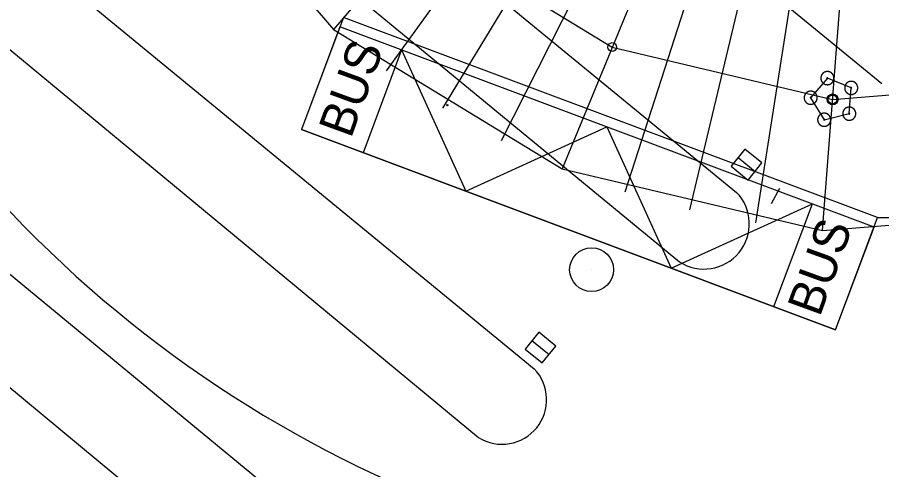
# Model space of a CAD drawing. Extents: x -438303 to -437792, y -1133191 to -1132731.
# Drawn here: x -438077.75 to -438058.05, y -1132976.36 to -1132966.05 of the extents above; entities that cross this region are included whole.
import ezdxf

# ---------------------------------------------------------------- set-up
doc = ezdxf.new("R2010")
doc.units = 0
for name, color, linetype in [('MOBILIÁŘ', 7, 'Continuous'), ('OSY', 7, 'Continuous'), ('SILNA 1', 7, 'Continuous'), ('SILNA 2', 7, 'Continuous'), ('TENKA', 7, 'Continuous'), ('Vrstva 1', 7, 'Continuous'), ('Vrstva 10', 7, 'Continuous'), ('Vrstva 27', 7, 'Continuous')]:
    doc.layers.add(name, color=color, linetype=linetype)

# ---------------------------------------------------------------- blocks, each defined once
blk = doc.blocks.new('A$C32EE4163')
at = {"layer": 'SILNA 1'}
for radius in [1.25, 1.25, 1.13, 1.13]:
    blk.add_circle((0, 0), radius, dxfattribs=at)
blk = doc.blocks.new('A$C7A6F5A01')
at = {"layer": 'Vrstva 1'}
for p, q in [((-20, 32), (-39, 0)), ((-39, 0), (-20, -35)), ((18, 32), (-20, 32)), ((40, 0), (18, 32)), ((18, -35), (40, 0)), ((-20, -35), (18, -35))]:
    blk.add_line(p, q, dxfattribs=at)
for points in [[(1497, 0), (1491, 133), (1481, 203), (1479, 219), (1476, 236), (1474, 253), (1471, 269), (1468, 286), (1465, 302), (1461, 319), (1458, 335), (1454, 351), (1450, 367), (1446, 383), (1442, 399), (1437, 415), (1432, 431), (1428, 447), (1423, 463), (1418, 478), (1412, 494), (1407, 509), (1401, 524), (1396, 540), (1390, 555), (1383, 570), (1377, 585), (1371, 600), (1364, 615), (1358, 630), (1351, 644), (1344, 659), (1336, 673), (1329, 688), (1322, 702), (1314, 716), (1306, 730), (1298, 744), (1290, 758), (1282, 772), (1274, 786), (1265, 799), (1256, 813), (1248, 826), (1239, 840), (1229, 853), (1220, 866), (1211, 879), (1201, 892), (1192, 905), (1182, 917), (1172, 930), (1162, 942), (1152, 955), (1142, 967), (1131, 979), (1121, 991), (1110, 1003), (1099, 1015), (1088, 1026), (1077, 1038), (1066, 1049), (1055, 1061), (1044, 1072), (1032, 1083), (1020, 1094), (1009, 1105), (997, 1115), (985, 1126), (973, 1136), (961, 1147), (948, 1157), (936, 1167), (923, 1177), (911, 1186), (898, 1196), (885, 1206), (872, 1215), (859, 1224), (846, 1233), (833, 1242), (819, 1251), (806, 1260), (792, 1268), (779, 1277), (765, 1285), (751, 1293), (737, 1301), (723, 1309), (709, 1317), (695, 1324), (681, 1332), (666, 1339), (652, 1346), (637, 1353), (623, 1360), (608, 1366), (593, 1373), (578, 1379), (563, 1385), (548, 1391), (533, 1397), (518, 1403), (503, 1409), (487, 1414), (472, 1419), (456, 1424), (441, 1429), (425, 1434), (409, 1438), (394, 1443), (378, 1447), (362, 1451), (346, 1455), (330, 1459), (314, 1462), (298, 1466), (281, 1469), (265, 1472), (249, 1475), (232, 1478), (216, 1480), (200, 1482), (183, 1485), (166, 1487), (150, 1488), (133, 1490), (116, 1491), (99, 1493), (83, 1494), (66, 1495), (-67, 1495), (-85, 1494), (-102, 1493), (-120, 1491), (-137, 1490), (-154, 1488), (-172, 1486), (-189, 1484), (-206, 1482), (-223, 1479), (-240, 1477), (-257, 1474), (-274, 1471), (-290, 1467), (-307, 1464), (-324, 1460), (-341, 1457), (-357, 1453), (-374, 1448), (-390, 1444), (-406, 1440), (-422, 1435), (-439, 1430), (-455, 1425), (-471, 1420), (-487, 1414), (-503, 1409), (-518, 1403), (-534, 1397), (-550, 1391), (-565, 1385), (-581, 1378), (-596, 1372), (-611, 1365), (-626, 1358), (-642, 1351), (-657, 1344), (-671, 1336), (-686, 1329), (-701, 1321), (-716, 1313), (-730, 1305), (-744, 1297), (-759, 1289), (-773, 1280), (-787, 1272), (-801, 1263), (-815, 1254), (-829, 1245), (-843, 1236), (-856, 1226), (-870, 1217), (-883, 1207), (-896, 1197), (-909, 1187), (-922, 1177), (-935, 1167), (-948, 1156), (-961, 1146), (-973, 1135), (-986, 1124), (-998, 1114), (-1010, 1102), (-1023, 1091), (-1035, 1080), (-1046, 1069), (-1058, 1057), (-1070, 1045), (-1081, 1033), (-1092, 1021), (-1104, 1009), (-1115, 997), (-1126, 985), (-1136, 972), (-1147, 960), (-1158, 947), (-1168, 934), (-1178, 921), (-1188, 908), (-1198, 895), (-1208, 882), (-1218, 869), (-1227, 855), (-1237, 841), (-1246, 828), (-1255, 814), (-1264, 800), (-1273, 786), (-1281, 772), (-1290, 758), (-1298, 743), (-1306, 729), (-1314, 714), (-1322, 700), (-1330, 685), (-1338, 670), (-1345, 655), (-1352, 640), (-1359, 625), (-1366, 610), (-1373, 594), (-1379, 579), (-1386, 564), (-1392, 548), (-1398, 532), (-1404, 517), (-1410, 501), (-1415, 485), (-1420, 469), (-1426, 453), (-1431, 437), (-1435, 420), (-1440, 404), (-1445, 388), (-1449, 371), (-1453, 355), (-1457, 338), (-1461, 321), (-1464, 304), (-1467, 288), (-1471, 271), (-1474, 254), (-1476, 237), (-1479, 220), (-1481, 202), (-1484, 185), (-1486, 168), (-1487, 150), (-1489, 133), (-1495, 67), (-1495, -66), (-1489, -136), (-1488, -153), (-1486, -170), (-1484, -186), (-1482, -203), (-1479, -220), (-1477, -236), (-1474, -253), (-1472, -269), (-1469, -285), (-1465, -302), (-1462, -318), (-1458, -334), (-1455, -350), (-1451, -366), (-1447, -382), (-1442, -398), (-1438, -414), (-1433, -429), (-1429, -445), (-1424, -461), (-1419, -476), (-1413, -492), (-1408, -507), (-1402, -522), (-1397, -537), (-1391, -552), (-1385, -568), (-1378, -582), (-1372, -597), (-1366, -612), (-1359, -627), (-1352, -641), (-1345, -656), (-1338, -670), (-1330, -685), (-1323, -699), (-1315, -713), (-1308, -727), (-1300, -741), (-1292, -755), (-1283, -769), (-1275, -783), (-1267, -796), (-1258, -810), (-1249, -823), (-1240, -837), (-1231, -850), (-1222, -863), (-1213, -876), (-1203, -889), (-1193, -902), (-1184, -914), (-1174, -927), (-1164, -939), (-1154, -952), (-1143, -964), (-1133, -976), (-1122, -988), (-1112, -1000), (-1101, -1012), (-1090, -1024), (-1079, -1035), (-1068, -1047), (-1057, -1058), (-1045, -1069), (-1034, -1080), (-1022, -1091), (-1010, -1102), (-999, -1113), (-987, -1124), (-974, -1134), (-962, -1145), (-950, -1155), (-938, -1165), (-925, -1175), (-912, -1185), (-900, -1194), (-887, -1204), (-874, -1213), (-861, -1223), (-848, -1232), (-834, -1241), (-821, -1250), (-808, -1259), (-794, -1267), (-780, -1276), (-767, -1284), (-753, -1292), (-739, -1300), (-725, -1308), (-711, -1316), (-696, -1324), (-682, -1331), (-668, -1338), (-653, -1346), (-639, -1353), (-624, -1360), (-609, -1366), (-595, -1373), (-580, -1379), (-565, -1385), (-550, -1392), (-534, -1397), (-519, -1403), (-504, -1409), (-489, -1414), (-473, -1420), (-458, -1425), (-442, -1430), (-426, -1434), (-411, -1439), (-395, -1444), (-379, -1448), (-363, -1452), (-347, -1456), (-331, -1460), (-315, -1463), (-299, -1467), (-283, -1470), (-266, -1473), (-250, -1476), (-233, -1479), (-217, -1481), (-200, -1484), (-184, -1486), (-167, -1488), (-151, -1490), (-134, -1491), (-67, -1495), (-1, -1495), (17, -1495), (34, -1494), (51, -1494), (68, -1494), (85, -1493), (103, -1492), (120, -1491), (137, -1489), (154, -1488), (171, -1486), (188, -1484), (204, -1482), (221, -1480), (238, -1477), (255, -1474), (271, -1471), (288, -1468), (305, -1465), (321, -1461), (338, -1458), (354, -1454), (370, -1450), (387, -1446), (403, -1441), (419, -1436), (435, -1432), (451, -1427), (467, -1422), (483, -1416), (498, -1411), (514, -1405), (530, -1399), (545, -1393), (561, -1387), (576, -1381), (592, -1374), (607, -1367), (622, -1361), (637, -1354), (652, -1346), (667, -1339), (682, -1331), (697, -1324), (711, -1316), (726, -1308), (740, -1300), (755, -1291), (769, -1283), (783, -1274), (797, -1265), (811, -1257), (825, -1247), (839, -1238), (852, -1229), (866, -1219), (879, -1210), (893, -1200), (906, -1190), (919, -1180), (932, -1169), (945, -1159), (958, -1149), (970, -1138), (983, -1127), (995, -1116), (1008, -1105), (1020, -1094), (1032, -1082), (1044, -1071), (1056, -1059), (1067, -1048), (1079, -1036), (1090, -1024), (1102, -1012), (1113, -999), (1124, -987), (1135, -975), (1146, -962), (1156, -949), (1167, -936), (1177, -923), (1187, -910), (1197, -897), (1207, -884), (1217, -870), (1227, -857), (1236, -843), (1246, -830), (1255, -816), (1264, -802), (1273, -788), (1281, -773), (1290, -759), (1298, -745), (1307, -730), (1315, -716), (1323, -701), (1330, -686), (1338, -671), (1346, -656), (1353, -641), (1360, -626), (1367, -611), (1374, -595), (1380, -580), (1387, -564), (1393, -549), (1399, -533), (1405, -517), (1410, -501), (1416, -486), (1421, -469), (1427, -453), (1431, -437), (1436, -421), (1441, -405), (1445, -388), (1450, -372), (1454, -355), (1457, -338), (1461, -322), (1465, -305), (1468, -288), (1471, -271), (1474, -254), (1476, -237), (1479, -220), (1481, -203), (1491, -136), (1494, -66)], [(-1, -101), (18, -98), (37, -92), (39, -91), (41, -90), (43, -89), (45, -88), (47, -87), (49, -86), (51, -85), (53, -84), (55, -83), (57, -82), (58, -81), (60, -80), (62, -78), (63, -77), (65, -76), (67, -75), (68, -73), (70, -72), (71, -70), (73, -69), (74, -68), (75, -66), (77, -65), (78, -63), (79, -62), (80, -60), (82, -59), (83, -57), (84, -55), (85, -54), (86, -52), (87, -50), (88, -49), (89, -47), (90, -45), (90, -44), (91, -42), (92, -40), (93, -38), (94, -37), (94, -35), (95, -33), (95, -31), (96, -29), (97, -28), (97, -26), (98, -24), (98, -22), (98, -20), (99, -18), (99, -16), (99, -15), (100, -13), (100, -11), (100, -9), (100, -7), (100, -5), (100, -3), (100, -1), (100, 1), (100, 2), (100, 4), (100, 6), (100, 8), (100, 10), (100, 12), (99, 14), (99, 16), (99, 18), (98, 19), (98, 21), (98, 23), (97, 25), (97, 27), (96, 29), (95, 31), (95, 32), (94, 34), (94, 36), (93, 38), (92, 40), (91, 41), (91, 43), (90, 45), (89, 47), (88, 48), (87, 50), (86, 52), (85, 53), (84, 55), (83, 57), (82, 58), (81, 60), (79, 61), (78, 63), (77, 64), (76, 66), (74, 67), (73, 69), (71, 70), (70, 72), (69, 73), (67, 74), (66, 76), (64, 77), (62, 78), (61, 79), (59, 81), (57, 82), (56, 83), (54, 84), (52, 85), (50, 86), (48, 87), (46, 88), (44, 89), (42, 90), (40, 91), (38, 92), (36, 93), (34, 94), (32, 94), (30, 95), (27, 96), (25, 96), (23, 97), (21, 98), (18, 98), (-17, 98), (-19, 98), (-21, 97), (-23, 96), (-26, 96), (-28, 95), (-30, 94), (-32, 94), (-34, 93), (-36, 92), (-38, 91), (-40, 90), (-42, 89), (-44, 88), (-46, 87), (-48, 86), (-50, 85), (-52, 84), (-54, 83), (-55, 82), (-57, 81), (-59, 80), (-60, 78), (-62, 77), (-64, 76), (-65, 75), (-67, 73), (-68, 72), (-70, 71), (-71, 69), (-72, 68), (-74, 66), (-75, 65), (-76, 63), (-78, 62), (-79, 60), (-80, 59), (-81, 57), (-82, 56), (-83, 54), (-85, 52), (-86, 51), (-87, 49), (-87, 47), (-88, 46), (-89, 44), (-90, 42), (-91, 41), (-92, 39), (-92, 37), (-93, 35), (-94, 34), (-94, 32), (-95, 30), (-96, 28), (-96, 26), (-97, 25), (-97, 23), (-98, 21), (-98, 19), (-98, 17), (-99, 15), (-99, 13), (-99, 12), (-99, 10), (-100, 8), (-100, 6), (-100, 4), (-100, 2), (-100, 0), (-100, -2), (-100, -3), (-100, -5), (-100, -7), (-100, -9), (-99, -11), (-99, -13), (-99, -15), (-99, -17), (-98, -18), (-98, -20), (-98, -22), (-97, -24), (-97, -26), (-96, -28), (-96, -29), (-95, -31), (-94, -33), (-94, -35), (-93, -37), (-92, -38), (-92, -40), (-91, -42), (-90, -44), (-89, -45), (-88, -47), (-87, -49), (-86, -50), (-85, -52), (-84, -54), (-83, -55), (-82, -57), (-80, -58), (-79, -60), (-78, -62), (-77, -63), (-75, -65), (-74, -66), (-72, -68), (-71, -69), (-70, -71), (-68, -72), (-66, -73), (-65, -75), (-63, -76), (-61, -77), (-60, -79), (-58, -80), (-56, -81), (-54, -82), (-52, -83), (-50, -85), (-48, -86), (-46, -87), (-44, -88), (-42, -89), (-40, -90), (-38, -91), (-36, -92), (-17, -98)]]:
    blk.add_lwpolyline(points, close=True, dxfattribs=at)
blk = doc.blocks.new('A$C5CBC2F6B')
at = {"layer": 'DEFPOINTS'}
blk.add_lwpolyline([(0, 5), (-4.76, 1.55), (-2.94, -4.05), (2.94, -4.05), (4.76, 1.55)], close=True, dxfattribs=at)
at = {"layer": 'MOBILIÁŘ', "xscale": 0.001, "yscale": 0.001}
for p in [(0, 5), (-4.75, 1.55), (4.76, 1.55), (-2.94, -4.05), (2.94, -4.05)]:
    blk.add_blockref('A$C7A6F5A01', p, dxfattribs=at)
blk = doc.blocks.new('A$C6C6266F8')
at = {"layer": 'OSY'}
for p, q in [((-80.9, -58.78), (-157.76, -114.62)), ((-148.28, -126.64), (-76.04, -64.94)), ((-70.71, -70.71), (-137.89, -137.89)), ((-64.94, -76.04), (-126.64, -148.28)), ((-58.78, -80.9), (-114.62, -157.76)), ((-101.89, -166.26), (-52.25, -85.26)), ((-88.53, -173.75), (-45.4, -89.1)), ((-74.62, -180.16), (-38.27, -92.39)), ((-60.26, -185.46), (-30.9, -95.11))]:
    blk.add_line(p, q, dxfattribs=at)

msp = doc.modelspace()

# ---------------------------------------------------------------- linework, layer by layer
at = {"layer": 'OSY'}
for points in [[(-438050.489, -1132933.436), (-438056.425, -1132932.025), (-438062.506, -1132932.517), (-438068.137, -1132934.864), (-438072.767, -1132938.837), (-438075.944, -1132944.046), (-438077.355, -1132949.981), (-438076.862, -1132956.062), (-438074.515, -1132961.694), (-438070.543, -1132966.324), (-438065.334, -1132969.5), (-438059.398, -1132970.911), (-438053.317, -1132970.419), (-438047.686, -1132968.072), (-438043.055, -1132964.099), (-438039.879, -1132958.89), (-438038.468, -1132952.955), (-438038.96, -1132946.874), (-438041.308, -1132941.242), (-438045.28, -1132936.612)], [(-438056.653, -1132935.016), (-438061.799, -1132935.433), (-438066.564, -1132937.419), (-438070.482, -1132940.78), (-438073.169, -1132945.188), (-438074.363, -1132950.21), (-438073.947, -1132955.356), (-438071.961, -1132960.121), (-438068.599, -1132964.039), (-438064.192, -1132966.726), (-438059.169, -1132967.92), (-438054.024, -1132967.504), (-438049.259, -1132965.517), (-438045.341, -1132962.156), (-438042.653, -1132957.748), (-438041.459, -1132952.726), (-438041.876, -1132947.581), (-438043.862, -1132942.816), (-438047.223, -1132938.898), (-438051.631, -1132936.21)], [(-438056.653, -1132935.016), (-438061.799, -1132935.433), (-438066.564, -1132937.419), (-438070.482, -1132940.78), (-438073.169, -1132945.188), (-438074.363, -1132950.21), (-438073.947, -1132955.356), (-438071.961, -1132960.121), (-438068.599, -1132964.039), (-438064.192, -1132966.726), (-438059.169, -1132967.92), (-438054.024, -1132967.504), (-438049.259, -1132965.517), (-438045.341, -1132962.156), (-438042.653, -1132957.748), (-438041.459, -1132952.726), (-438041.876, -1132947.581), (-438043.862, -1132942.816), (-438047.223, -1132938.898), (-438051.631, -1132936.21)]]:
    msp.add_lwpolyline(points, close=True, dxfattribs=at)
at = {"layer": 'SILNA 1'}
for centre in [(-438064.192, -1132966.726), (-438064.192, -1132966.726), (-438064.192, -1132966.726), (-438064.192, -1132966.726), (-438059.169, -1132967.92), (-438059.169, -1132967.92), (-438059.169, -1132967.92), (-438059.169, -1132967.92)]:
    msp.add_circle(centre, 0.1, dxfattribs=at)
at = {"layer": 'SILNA 2'}
msp.add_lwpolyline([(-438058.144, -1132970.613), (-438070.317, -1132966.051), (-438071.275, -1132968.608), (-438059.102, -1132973.17)], close=True, dxfattribs=at)
msp.add_lwpolyline([(-438058.144, -1132970.613), (-438070.317, -1132966.051), (-438071.275, -1132968.608), (-438059.102, -1132973.17)], close=True, dxfattribs=at)
at = {"layer": 'Vrstva 1'}
for p, q in [((-438070.398, -1132966.267), (-438071.275, -1132968.608)), ((-438070.398, -1132966.267), (-438071.275, -1132968.608)), ((-438058.225, -1132970.829), (-438070.398, -1132966.267)), ((-438058.225, -1132970.829), (-438070.398, -1132966.267)), ((-438068.994, -1132966.793), (-438069.871, -1132969.134)), ((-438068.994, -1132966.793), (-438069.871, -1132969.134)), ((-438058.049, -1132967.557), (-438058.049, -1132967.557)), ((-438073.452, -1132967.919), (-438073.452, -1132967.919)), ((-438059.102, -1132973.17), (-438071.275, -1132968.608)), ((-438059.102, -1132973.17), (-438071.275, -1132968.608)), ((-438074.732, -1132969.394), (-438074.732, -1132969.394)), ((-438061.13, -1132969.405), (-438061.13, -1132969.405)), ((-438060.565, -1132970.294), (-438060.374, -1132969.94)), ((-438060.565, -1132970.294), (-438060.374, -1132969.94)), ((-438061.357, -1132970.038), (-438061.357, -1132970.038)), ((-438060.507, -1132972.643), (-438059.63, -1132970.302)), ((-438060.507, -1132972.643), (-438059.63, -1132970.302)), ((-438059.102, -1132973.17), (-438058.225, -1132970.829)), ((-438059.102, -1132973.17), (-438058.225, -1132970.829)), ((-438063.385, -1132971.022), (-438063.385, -1132971.022)), ((-438061.314, -1132971.424), (-438061.314, -1132971.424)), ((-438064.662, -1132971.802), (-438064.662, -1132971.802)), ((-438065.825, -1132973.577), (-438065.825, -1132973.577)), ((-438065.971, -1132974.061), (-438065.971, -1132974.061)), ((-438065.862, -1132975.336), (-438065.862, -1132975.336)), ((-438067.238, -1132975.626), (-438067.238, -1132975.626))]:
    msp.add_line(p, q, dxfattribs=at)
msp.add_lwpolyline([(-438068.994, -1132966.793), (-438067.53, -1132970.011), (-438064.312, -1132968.548), (-438062.848, -1132971.766), (-438059.63, -1132970.302)], dxfattribs=at)
msp.add_lwpolyline([(-438068.994, -1132966.793), (-438067.53, -1132970.011), (-438064.312, -1132968.548), (-438062.848, -1132971.766), (-438059.63, -1132970.302)], dxfattribs=at)
msp.add_circle((-438067.95, -1132968.051), 0.0127, dxfattribs=at)
msp.add_circle((-438067.95, -1132968.051), 0.0127, dxfattribs=at)
for centre, radius, start, end in [((-438057.911, -1132951.468), 27.6, 199.6428, 254.4643), ((-438057.911, -1132951.468), 27.6, 199.6428, 254.4643), ((-438057.911, -1132951.464), 19.15, 269.2928, 283.6167), ((-438057.911, -1132951.464), 19.15, 269.2928, 283.6167)]:
    msp.add_arc(centre, radius, start, end, dxfattribs=at)
at = {"layer": 'Vrstva 10'}
for points in [[(-438074.666, -1132953.935), (-438058.049, -1132967.557)], [(-438077.751, -1132956.582), (-438061.357, -1132970.038)], [(-438079.155, -1132958.045), (-438062.658, -1132971.62)], [(-438082.344, -1132960.614), (-438065.971, -1132974.061)], [(-438083.714, -1132961.987), (-438067.238, -1132975.626)], [(-438086.852, -1132964.524), (-438070.491, -1132978.033)], [(-438088.005, -1132966.118), (-438071.79, -1132979.58)]]:
    msp.add_lwpolyline(points, dxfattribs=at)
for centre, radius, start, end in [((-438062.098, -1132970.755), 1.031, 237.0717, 44.0342), ((-438066.701, -1132974.765), 1.015, 238.0779, 43.9399)]:
    msp.add_arc(centre, radius, start, end, dxfattribs=at)
at = {"layer": 'Vrstva 27'}
for p, q in [((-438061.324, -1132969.247), (-438060.936, -1132969.563)), ((-438066.02, -1132973.419), (-438065.631, -1132973.734))]:
    msp.add_line(p, q, dxfattribs=at)
for points in [[(-438061.482, -1132969.441), (-438061.094, -1132969.757), (-438060.778, -1132969.369), (-438061.166, -1132969.053)], [(-438066.177, -1132973.612), (-438065.79, -1132973.928), (-438065.473, -1132973.541), (-438065.861, -1132973.225)]]:
    msp.add_lwpolyline(points, close=True, dxfattribs=at)
msp.add_circle((-438064.662, -1132971.802), 0.5, dxfattribs=at)

# ---------------------------------------------------------------- block references
at = {"layer": 'MOBILIÁŘ', "xscale": 0.10000000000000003, "yscale": 0.10000000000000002, "rotation": 13.627557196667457}
msp.add_blockref('A$C5CBC2F6B', (-438059.17, -1132967.92), dxfattribs=at)
msp.add_blockref('A$C5CBC2F6B', (-438059.17, -1132967.92), dxfattribs=at)
at = {"layer": 'OSY', "xscale": 0.10000000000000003, "yscale": 0.10000000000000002, "rotation": 13.627557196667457}
msp.add_blockref('A$C6C6266F8', (-438057.911, -1132951.468), dxfattribs=at)
at = {"layer": 'TENKA', "xscale": 0.1, "yscale": 0.10000000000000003, "rotation": 0.10416846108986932}
msp.add_blockref('A$C32EE4163', (-438059.169, -1132967.92), dxfattribs=at)
msp.add_blockref('A$C32EE4163', (-438059.169, -1132967.92), dxfattribs=at)

# ---------------------------------------------------------------- texts
at = {"layer": 'Vrstva 1'}
for p in [(-438070.149, -1132968.83), (-438070.149, -1132968.83), (-438059.464, -1132972.901), (-438059.464, -1132972.901)]:
    msp.add_text('BUS', height=0.8, rotation=69.9627, dxfattribs=at).set_placement(p)

doc.saveas('drawing.dxf')
